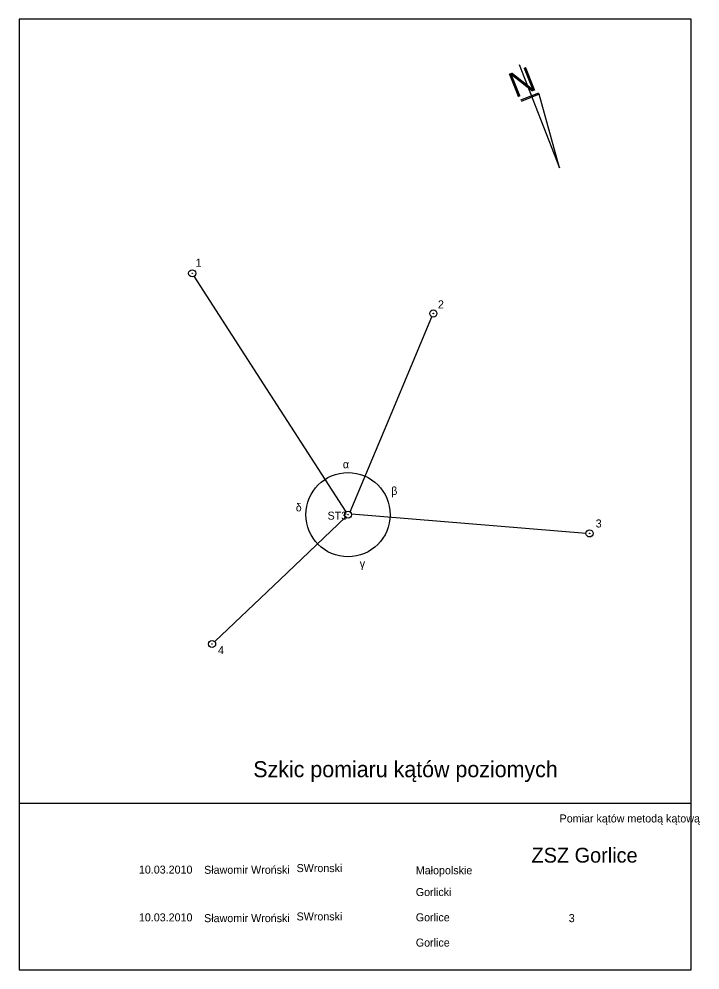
# Model space of a CAD drawing. Extents: x 4638556 to 4639783, y 5351940 to 5352237.
# Drawn here: x 4639065.1 to 4639277.8, y 5351939.6 to 5352236.6 of the extents above; entities that cross this region are included whole.
import ezdxf

# ---------------------------------------------------------------- set-up
doc = ezdxf.new("R2010")
doc.units = 0
doc.layers.add('Default', color=7, linetype='Continuous')

msp = doc.modelspace()

# ---------------------------------------------------------------- linework, layer by layer
at = {"layer": 'Default'}
for p, q in [((4639221.36, 5352222.44), (4639233.91, 5352190.14)), ((4639227.37, 5352213.5), (4639221.77, 5352211.28)), ((4639227.57, 5352213.12), (4639221.97, 5352210.89)), ((4639233.91, 5352190.14), (4639227.57, 5352213.12)), ((4639143.53, 5352119.5), (4639119.81, 5352156.25)), ((4639181.32, 5352113.16), (4639194.09, 5352143.61)), ((4639167.26, 5352082.75), (4639143.53, 5352119.5)), ((4639168.54, 5352082.7), (4639181.32, 5352113.16)), ((4639167.06, 5352081.04), (4639146.63, 5352061.61)), ((4639168.94, 5352082.12), (4639205.59, 5352079.09)), ((4639205.59, 5352079.09), (4639242.23, 5352076.05)), ((4639146.63, 5352061.61), (4639126.21, 5352042.18))]:
    msp.add_line(p, q, dxfattribs=at)
for points in [[(4639065.08, 5351939.61), (4639275.08, 5351939.61), (4639275.08, 5352236.61), (4639065.08, 5352236.61)], [(4639065.08, 5351939.61), (4639275.08, 5351939.61), (4639275.08, 5351991.61), (4639065.08, 5351991.61)]]:
    msp.add_lwpolyline(points, close=True, dxfattribs=at)
for centre, radius in [((4639119.2, 5352157.19), 1.12), ((4639119.2, 5352157.19), 0.0804), ((4639194.52, 5352144.64), 1.12), ((4639194.52, 5352144.64), 0.0804), ((4639167.87, 5352081.81), 13.15), ((4639167.87, 5352081.81), 1.12), ((4639167.87, 5352081.81), 0.0804), ((4639243.34, 5352075.96), 1.12), ((4639243.34, 5352075.96), 0.0804), ((4639125.39, 5352041.42), 1.12), ((4639125.39, 5352041.42), 0.0804)]:
    msp.add_circle(centre, radius, dxfattribs=at)

# ---------------------------------------------------------------- texts
msp.add_text('N', height=7.81, rotation=201.6917, dxfattribs=at).set_placement((4639224.29, 5352221.95))
for s, height, p in [('1', 2.5, (4639120.24, 5352159.23)), ('2', 2.5, (4639195.96, 5352146.24)), ('α', 2.5, (4639166.26, 5352096.31)), ('β', 2.5, (4639181.36, 5352088.01)), ('δ', 2.5, (4639151.53, 5352082.85)), ('ST3', 2.5, (4639161.48, 5352080.26)), ('3', 2.5, (4639245.25, 5352077.82)), ('γ', 2.5, (4639171.53, 5352065.29)), ('4', 2.5, (4639127.26, 5352038.26)), ('Szkic pomiaru kątów poziomych', 5, (4639138.27, 5351999.82)), ('Pomiar kątów metodą kątową', 2.5, (4639233.98, 5351985.69)), ('ZSZ Gorlice', 4.6473, (4639225.2, 5351973.14)), ('SWronski', 2.5, (4639151.8, 5351970.18)), ('10.03.2010', 2.5, (4639102.54, 5351969.71)), ('Sławomir Wroński', 2.5, (4639122.92, 5351969.65)), ('Małopolskie', 2.5, (4639189.05, 5351969.5)), ('Gorlicki', 2.5, (4639189.05, 5351962.7)), ('10.03.2010', 2.5, (4639102.54, 5351954.79)), ('Sławomir Wroński', 2.5, (4639122.92, 5351954.55)), ('SWronski', 2.5, (4639151.8, 5351955.08)), ('Gorlice', 2.5, (4639189.05, 5351954.81)), ('3', 2.5, (4639236.83, 5351954.55)), ('Gorlice', 2.5, (4639189.05, 5351946.92))]:
    msp.add_text(s, height=height, dxfattribs=at).set_placement(p)

doc.saveas('drawing.dxf')
